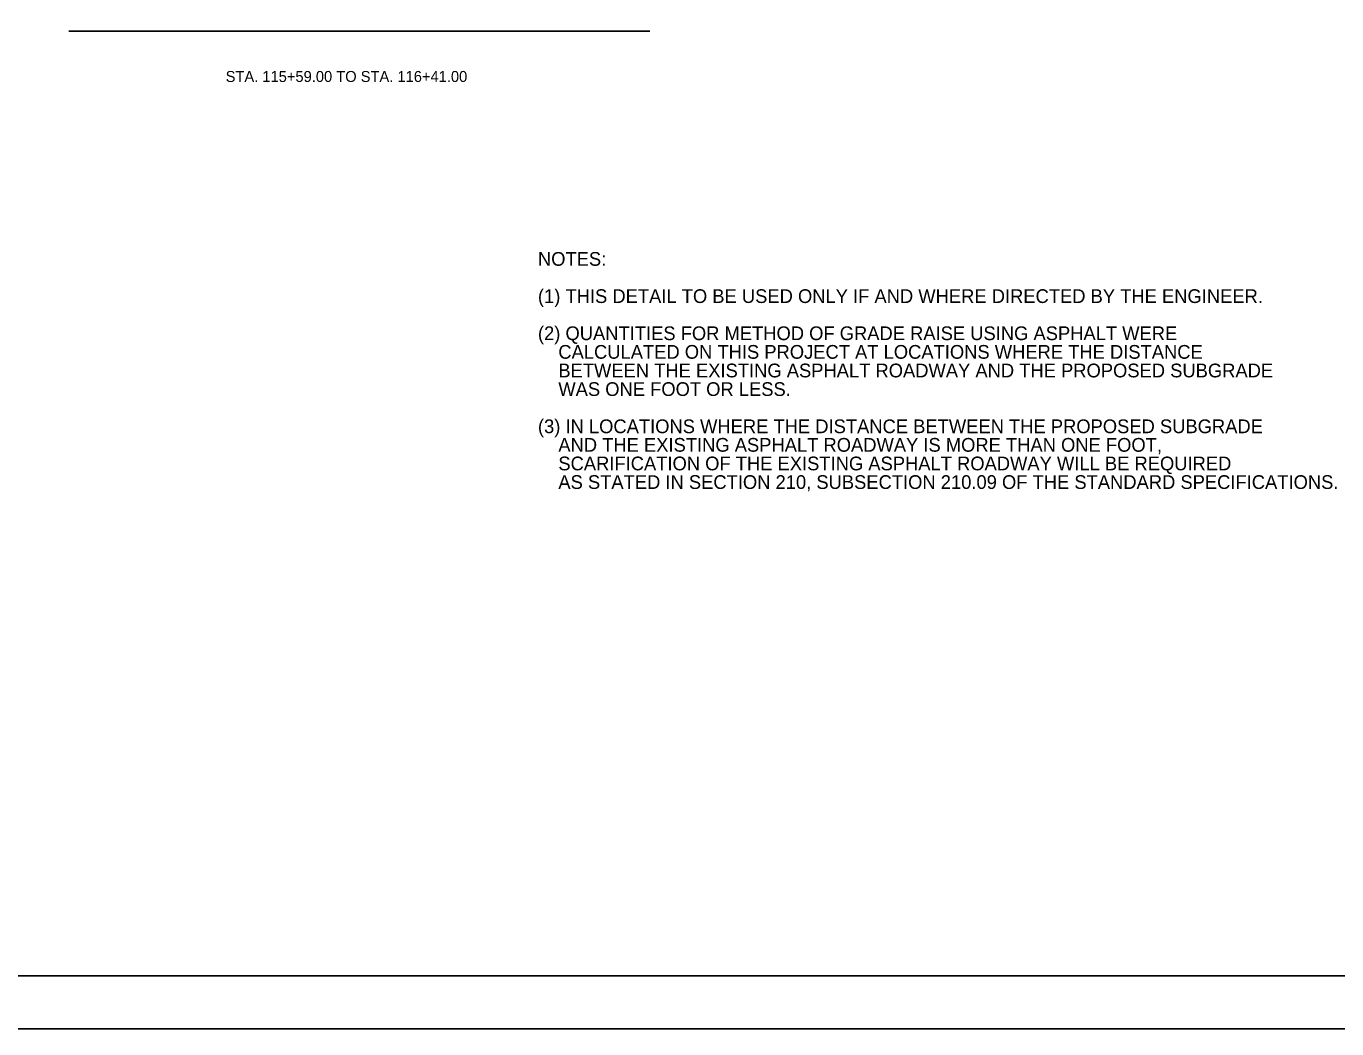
# Model space of a CAD drawing. Extents: x 438659 to 573674, y 10724 to 98600.
# Drawn here: x 502705 to 519895, y 52630 to 65775 of the extents above; entities that cross this region are included whole.
import ezdxf

# ---------------------------------------------------------------- set-up
doc = ezdxf.new("R2010")
doc.units = 0
for name, color, linetype in [('border', 7, 'Continuous'), ('R_Striping', 7, 'Continuous'), ('T_Vehicle Path Rt', 7, 'Continuous')]:
    doc.layers.add(name, color=color, linetype=linetype)

msp = doc.modelspace()

# ---------------------------------------------------------------- linework, layer by layer
at = {"layer": 'border'}
msp.add_line((503264, 65711), (510886, 65711), dxfattribs=at)
at = {"layer": 'R_Striping'}
msp.add_line((525874, 53322), (487586, 53322), dxfattribs=at)
for points in [[(526566, 79030), (485766, 79030), (485766, 52630), (526566, 52630)], [(487586, 53322), (487586, 78338), (516003, 78338), (516003, 77152), (520702, 77152), (520702, 76802), (525874, 76802), (525874, 53322)]]:
    msp.add_lwpolyline(points, close=True, dxfattribs=at)

# ---------------------------------------------------------------- texts
at = {"layer": 'border'}
msp.add_text('STA. 115+59.00 TO STA. 116+41.00', height=144, dxfattribs=at).set_placement((505321, 65044))
at = {"layer": 'T_Vehicle Path Rt'}
for s, p in [('NOTES:', (509417, 62634)), ('(1) THIS DETAIL TO BE USED ONLY IF AND WHERE DIRECTED BY THE ENGINEER.', (509417, 62146)), ('(2) QUANTITIES FOR METHOD OF GRADE RAISE USING ASPHALT WERE', (509417, 61659)), ('    CALCULATED ON THIS PROJECT AT LOCATIONS WHERE THE DISTANCE', (509417, 61415)), ('    BETWEEN THE EXISTING ASPHALT ROADWAY AND THE PROPOSED SUBGRADE', (509417, 61171)), ('    WAS ONE FOOT OR LESS.', (509417, 60927)), ('(3) IN LOCATIONS WHERE THE DISTANCE BETWEEN THE PROPOSED SUBGRADE', (509417, 60439)), ('    AND THE EXISTING ASPHALT ROADWAY IS MORE THAN ONE FOOT,', (509417, 60196)), ('    SCARIFICATION OF THE EXISTING ASPHALT ROADWAY WILL BE REQUIRED', (509417, 59952)), ('    AS STATED IN SECTION 210, SUBSECTION 210.09 OF THE STANDARD SPECIFICATIONS.', (509417, 59708))]:
    msp.add_text(s, height=180, dxfattribs=at).set_placement(p)

doc.saveas('drawing.dxf')
